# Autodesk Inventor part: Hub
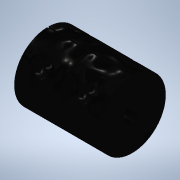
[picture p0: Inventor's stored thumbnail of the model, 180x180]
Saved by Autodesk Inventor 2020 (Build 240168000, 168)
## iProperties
Created: 2023-10
Part Number: Hub
Material: Générique
Document SubType Name: Modeling
Designer: bruno
Density: 1 g/cm^3
Appearance: Noir
Author: bruno
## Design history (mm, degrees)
sketch "Esquisse1"
  geometry: C1 r 10 at (0, 0); C2 r 2.5 at (0, 0); 1 further point
  constraints: 2 centre point, 2 coincident
  dimensions: "d0" = 20 diameter of C1; "d1" = 5 diameter of C2
extrude "Extrusion1" new body sketch "Esquisse1" stored distance "d2" = 25; taper "d3" = 0 deg
sketch "Esquisse2"
  geometry: L1 (-15.081, 11.256)-(25.844, 11.256); L2 (25.844, 11.256)-(25.844, 1.363); L3 (25.844, 1.363)-(-15.081, 1.363); L4 (-15.081, 1.363)-(-15.081, 11.256); 1 further point
  constraints: 8 end point, 2 parallel, 1 horizontal, 1 perpendicular
extrude "Extrusion2" cut sketch "Esquisse2" stored distance "d4" = 0.5; taper "d5" = 0 deg
sketch "Esquisse3"
  geometry: L1 (11.282, 0)-(-12.853, 0); L2 (-12.853, 0)-(-12.853, 13.498); L3 (-12.853, 13.498)-(11.282, 13.498); L4 (11.282, 13.498)-(11.282, 0); 1 further point
  constraints: 8 end point, 2 parallel, 1 horizontal, 1 perpendicular
extrude "Extrusion3" cut sketch "Esquisse3" distance "d6" = 0.5; taper "d7" = 0 deg
sketch "Esquisse4"
  geometry: L1 (-12.5, 9.997)-(-12.5, -10) reference; L2 (-12.5, 9.997)-(-0.5, 2.482); L3 (-0.5, 9.997)-(-0.5, -10) reference; L4 (12.5, -10)-(12.5, 9.997) reference; L5 (0, 2.482)-(12.5, 9.997); C1 r 1.5 at (-6.5, 6.239); C2 r 1.5 at (6.25, 6.239); 1 further point
  constraints: 4 end point, 2 centre point, 2 midpoint, 1 point on line
  dimensions: "d8" = 3 diameter of C1; "d9" = 3 diameter of C2
extrude "Extrusion4" cut sketch "Esquisse4" stored distance "d10" = 100; taper "d11" = 0 deg
node "Plan de construction1"
sketch "Esquisse5"
  geometry: C1 r 2 at (-6.25, 6.239); C2 r 2 at (6.5, 6.239); 4 further points
  constraints: 2 centre point, 1 coincident, 1 vertical alignment, 2 other
  dimensions: "d13" = 4 diameter of C1; "d14" = 4 diameter of C2
extrude "Extrusion5" cut sketch "Esquisse5" distance "d15" = 100; taper "d16" = 0 deg
node "Solide1"
other parameters: "d12" = 6.25
